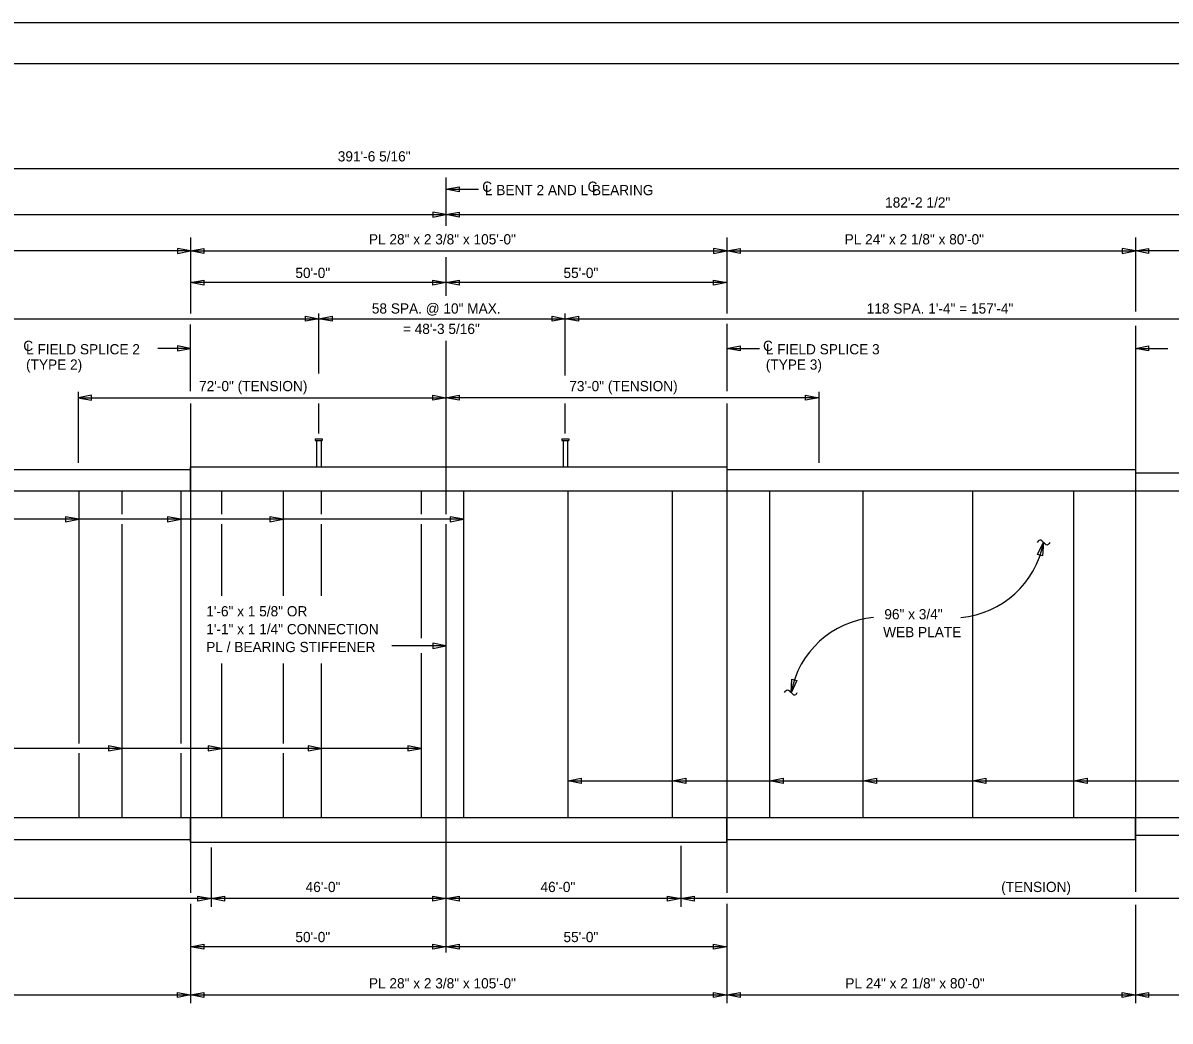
# Model space of a CAD drawing. Extents: x -305 to -161, y -187 to -99.
# Drawn here: x -251.8 to -195.7, y -148.4 to -99.5 of the extents above; entities that cross this region are included whole.
import ezdxf

# ---------------------------------------------------------------- set-up
doc = ezdxf.new("R2010")
doc.units = 0
for name, color, linetype in [('BR_AUTO DIMENSION', 7, 'Continuous'), ('BR_BORDER LINES', 7, 'Continuous'), ('BR_CENTER LINES', 7, 'Continuous'), ('BR_STRUCTURAL STEEL', 7, 'Continuous'), ('BR_TEXT', 7, 'Continuous'), ('Default', 7, 'Continuous'), ('Level 31', 7, 'Continuous')]:
    doc.layers.add(name, color=color, linetype=linetype)

msp = doc.modelspace()

# ---------------------------------------------------------------- linework, layer by layer
at = {"layer": 'BR_AUTO DIMENSION'}
for p, q in [((-284.516, -106.618), (-184.885, -106.618)), ((-231.124, -107.634), (-229.526, -107.634)), ((-284.516, -108.876), (-231.124, -108.876)), ((-231.124, -108.876), (-184.885, -108.876)), ((-243.624, -110.653), (-269.874, -110.653)), ((-243.624, -110.653), (-217.374, -110.653)), ((-217.374, -110.653), (-197.374, -110.653)), ((-184.885, -110.653), (-197.374, -110.653)), ((-231.124, -112.204), (-243.624, -112.204)), ((-217.374, -112.204), (-231.124, -112.204)), ((-278.349, -113.971), (-237.349, -113.971)), ((-237.349, -116.66), (-237.349, -113.721)), ((-237.349, -113.971), (-225.281, -113.971)), ((-225.281, -116.761), (-225.281, -113.721)), ((-225.281, -113.971), (-186.385, -113.971)), ((-243.624, -115.428), (-245.223, -115.428)), ((-217.374, -115.428), (-215.776, -115.428)), ((-197.374, -115.428), (-195.776, -115.428)), ((-249.124, -117.55), (-249.124, -121.025)), ((-249.124, -117.84), (-231.124, -117.84)), ((-212.874, -117.84), (-231.124, -117.84)), ((-212.874, -117.55), (-212.874, -121.025)), ((-237.349, -119.6), (-237.349, -118.13)), ((-225.281, -119.6), (-225.281, -118.13)), ((-230.266, -123.792), (-287.874, -123.792)), ((-231.124, -129.991), (-233.773, -129.991)), ((-232.34, -135.013), (-287.874, -135.013)), ((-225.147, -136.601), (-181.335, -136.601)), ((-219.624, -139.78), (-219.624, -142.773)), ((-242.624, -139.874), (-242.624, -142.773)), ((-242.624, -142.367), (-284.516, -142.367)), ((-231.124, -142.367), (-242.624, -142.367)), ((-219.624, -142.367), (-231.124, -142.367)), ((-184.885, -142.367), (-219.624, -142.367)), ((-231.124, -144.726), (-243.624, -144.726)), ((-217.374, -144.726), (-231.124, -144.726)), ((-269.874, -147.085), (-243.624, -147.085)), ((-243.624, -147.085), (-217.374, -147.085)), ((-217.374, -147.085), (-197.374, -147.085)), ((-197.374, -147.085), (-184.885, -147.085))]:
    msp.add_line(p, q, dxfattribs=at)
for points in [[(-230.474, -107.759), (-231.124, -107.634), (-230.474, -107.509)], [(-231.774, -109.001), (-231.124, -108.876), (-231.774, -108.751)], [(-230.474, -109.001), (-231.124, -108.876), (-230.474, -108.751)], [(-244.274, -110.778), (-243.624, -110.653), (-244.274, -110.528)], [(-242.974, -110.778), (-243.624, -110.653), (-242.974, -110.528)], [(-218.024, -110.778), (-217.374, -110.653), (-218.024, -110.528)], [(-216.724, -110.778), (-217.374, -110.653), (-216.724, -110.528)], [(-198.024, -110.778), (-197.374, -110.653), (-198.024, -110.528)], [(-196.724, -110.778), (-197.374, -110.653), (-196.724, -110.528)], [(-242.974, -112.329), (-243.624, -112.204), (-242.974, -112.079)], [(-231.774, -112.079), (-231.124, -112.204), (-231.774, -112.329)], [(-230.474, -112.329), (-231.124, -112.204), (-230.474, -112.079)], [(-218.024, -112.079), (-217.374, -112.204), (-218.024, -112.329)], [(-237.999, -113.846), (-237.349, -113.971), (-237.999, -114.096)], [(-236.699, -114.096), (-237.349, -113.971), (-236.699, -113.846)], [(-225.931, -113.846), (-225.281, -113.971), (-225.931, -114.096)], [(-224.631, -114.096), (-225.281, -113.971), (-224.631, -113.846)], [(-244.274, -115.553), (-243.624, -115.428), (-244.274, -115.303)], [(-216.724, -115.553), (-217.374, -115.428), (-216.724, -115.303)], [(-196.724, -115.553), (-197.374, -115.428), (-196.724, -115.303)], [(-248.474, -117.715), (-249.124, -117.84), (-248.474, -117.965)], [(-231.774, -117.715), (-231.124, -117.84), (-231.774, -117.965)], [(-230.474, -117.965), (-231.124, -117.84), (-230.474, -117.715)], [(-213.524, -117.715), (-212.874, -117.84), (-213.524, -117.965)], [(-249.749, -123.917), (-249.099, -123.792), (-249.749, -123.667)], [(-244.749, -123.917), (-244.099, -123.792), (-244.749, -123.667)], [(-239.749, -123.917), (-239.099, -123.792), (-239.749, -123.667)], [(-230.916, -123.917), (-230.266, -123.792), (-230.916, -123.667)], [(-202.159, -125.52), (-201.877, -124.922), (-201.917, -125.582)], [(-231.774, -130.116), (-231.124, -129.991), (-231.774, -129.866)], [(-213.946, -131.689), (-214.228, -132.287), (-214.188, -131.627)], [(-247.649, -135.138), (-246.999, -135.013), (-247.649, -134.888)], [(-242.763, -135.138), (-242.113, -135.013), (-242.763, -134.888)], [(-237.877, -135.138), (-237.227, -135.013), (-237.877, -134.888)], [(-232.99, -135.138), (-232.34, -135.013), (-232.99, -134.888)], [(-224.497, -136.726), (-225.147, -136.601), (-224.497, -136.476)], [(-219.378, -136.726), (-220.028, -136.601), (-219.378, -136.476)], [(-214.62, -136.726), (-215.27, -136.601), (-214.62, -136.476)], [(-210.045, -136.726), (-210.695, -136.601), (-210.045, -136.476)], [(-204.693, -136.726), (-205.343, -136.601), (-204.693, -136.476)], [(-199.729, -136.726), (-200.379, -136.601), (-199.729, -136.476)], [(-243.274, -142.242), (-242.624, -142.367), (-243.274, -142.492)], [(-241.974, -142.492), (-242.624, -142.367), (-241.974, -142.242)], [(-231.774, -142.242), (-231.124, -142.367), (-231.774, -142.492)], [(-230.474, -142.492), (-231.124, -142.367), (-230.474, -142.242)], [(-220.274, -142.242), (-219.624, -142.367), (-220.274, -142.492)], [(-218.974, -142.492), (-219.624, -142.367), (-218.974, -142.242)], [(-242.974, -144.851), (-243.624, -144.726), (-242.974, -144.601)], [(-231.774, -144.601), (-231.124, -144.726), (-231.774, -144.851)], [(-230.474, -144.851), (-231.124, -144.726), (-230.474, -144.601)], [(-218.024, -144.601), (-217.374, -144.726), (-218.024, -144.851)], [(-244.274, -146.96), (-243.624, -147.085), (-244.274, -147.21)], [(-242.974, -147.21), (-243.624, -147.085), (-242.974, -146.96)], [(-218.024, -146.96), (-217.374, -147.085), (-218.024, -147.21)], [(-216.724, -147.21), (-217.374, -147.085), (-216.724, -146.96)], [(-198.024, -146.96), (-197.374, -147.085), (-198.024, -147.21)], [(-196.724, -147.21), (-197.374, -147.085), (-196.724, -146.96)]]:
    msp.add_lwpolyline(points, close=True, dxfattribs=at)
for centre, start, end in [((-206.301, -124.118), 274.9624, 349.7037), ((-209.804, -133.091), 94.9624, 169.7037)]:
    msp.add_arc(centre, 4.497, start, end, dxfattribs=at)
at = {"layer": 'BR_BORDER LINES'}
msp.add_line((-163.178, -101.489), (-297.843, -101.489), dxfattribs=at)
at = {"layer": 'BR_CENTER LINES'}
for p, q in [((-231.124, -107.059), (-231.124, -109.43)), ((-243.624, -109.997), (-243.624, -113.711)), ((-217.374, -109.997), (-217.374, -113.711)), ((-197.374, -109.997), (-197.374, -113.625)), ((-231.124, -110.967), (-231.124, -112.846)), ((-243.645, -114.253), (-243.645, -117.526)), ((-217.374, -114.23), (-217.374, -117.526)), ((-197.374, -114.323), (-197.374, -142.045)), ((-231.124, -115.059), (-231.124, -122.412)), ((-243.624, -118.13), (-243.624, -124.614)), ((-217.374, -118.13), (-217.374, -126.436)), ((-243.624, -124.614), (-243.624, -142.086)), ((-217.374, -126.436), (-217.374, -142.086)), ((-231.124, -138.412), (-231.124, -145.014)), ((-243.624, -142.631), (-243.624, -147.486)), ((-217.374, -142.631), (-217.374, -147.486)), ((-197.374, -142.667), (-197.374, -147.486))]:
    msp.add_line(p, q, dxfattribs=at)
at = {"layer": 'BR_STRUCTURAL STEEL'}
for p, q in [((-243.624, -122.412), (-243.624, -121.225)), ((-243.624, -121.225), (-217.374, -121.225)), ((-217.374, -121.225), (-217.374, -122.412)), ((-269.874, -121.35), (-243.624, -121.35)), ((-217.374, -121.35), (-197.374, -121.35)), ((-197.374, -121.35), (-197.374, -122.412)), ((-184.885, -121.537), (-197.374, -121.537)), ((-184.885, -122.412), (-284.516, -122.412)), ((-249.099, -122.412), (-249.099, -134.771)), ((-246.999, -122.412), (-246.999, -123.55)), ((-244.099, -122.412), (-244.099, -134.771)), ((-242.113, -122.412), (-242.113, -123.55)), ((-239.099, -122.412), (-239.099, -127.548)), ((-237.227, -122.412), (-237.227, -123.55)), ((-232.34, -122.412), (-232.34, -123.55)), ((-231.124, -122.412), (-231.124, -123.55)), ((-230.266, -122.412), (-230.266, -138.412)), ((-225.147, -138.412), (-225.147, -122.412)), ((-220.028, -138.412), (-220.028, -122.412)), ((-215.27, -138.412), (-215.27, -122.412)), ((-210.695, -138.412), (-210.695, -122.412)), ((-205.343, -122.412), (-205.343, -138.412)), ((-200.379, -138.412), (-200.379, -122.412)), ((-246.999, -124.034), (-246.999, -138.412)), ((-242.113, -124.034), (-242.113, -127.548)), ((-237.227, -124.034), (-237.227, -127.548)), ((-232.34, -124.034), (-232.34, -129.618)), ((-231.124, -124.034), (-231.124, -138.412)), ((-232.34, -130.358), (-232.34, -138.412)), ((-242.113, -130.864), (-242.113, -138.412)), ((-239.099, -130.864), (-239.099, -134.771)), ((-237.227, -130.864), (-237.227, -138.412)), ((-249.099, -135.255), (-249.099, -138.412)), ((-244.099, -135.255), (-244.099, -138.412)), ((-239.099, -135.255), (-239.099, -138.412)), ((-184.885, -138.412), (-284.516, -138.412)), ((-243.624, -139.6), (-243.624, -138.412)), ((-217.374, -139.6), (-217.374, -138.412)), ((-197.374, -139.475), (-197.374, -138.412)), ((-269.874, -139.475), (-243.624, -139.475)), ((-243.624, -139.6), (-217.374, -139.6)), ((-217.374, -139.475), (-197.374, -139.475)), ((-184.885, -139.287), (-197.374, -139.287))]:
    msp.add_line(p, q, dxfattribs=at)
at = {"layer": 'BR_TEXT'}
for p, q in [((-202.137, -124.869), (-202.179, -124.93)), ((-201.795, -124.996), (-201.958, -124.847)), ((-201.562, -124.93), (-201.592, -124.976)), ((-214.543, -132.279), (-214.513, -132.233)), ((-214.31, -132.213), (-214.147, -132.362)), ((-213.968, -132.34), (-213.926, -132.279))]:
    msp.add_line(p, q, dxfattribs=at)
for centre, radius, start, end in [((-202.039, -124.922), 0.111, 43.4519, 151.7375), ((-201.702, -124.915), 0.125, 221.007, 330.8059), ((-214.403, -132.294), 0.125, 41.007, 150.8059), ((-214.066, -132.287), 0.111, 223.4519, 331.7375)]:
    msp.add_arc(centre, radius, start, end, dxfattribs=at)
at = {"layer": 'Default'}
for p, q in [((-237.521, -119.85), (-237.521, -119.944)), ((-237.521, -119.85), (-237.177, -119.85)), ((-237.521, -119.944), (-237.177, -119.944)), ((-237.459, -119.944), (-237.459, -121.225)), ((-237.24, -119.944), (-237.24, -121.225)), ((-237.177, -119.85), (-237.177, -119.944)), ((-225.453, -119.85), (-225.453, -119.944)), ((-225.453, -119.85), (-225.109, -119.85)), ((-225.453, -119.944), (-225.109, -119.944)), ((-225.39, -119.944), (-225.39, -121.225)), ((-225.171, -119.944), (-225.171, -121.225)), ((-225.109, -119.85), (-225.109, -119.944))]:
    msp.add_line(p, q, dxfattribs=at)
at = {"layer": 'Level 31'}
msp.add_lwpolyline([(-305.176, -187.489), (-161.176, -187.489), (-161.176, -99.489), (-305.176, -99.489)], close=True, dxfattribs=at)

# ---------------------------------------------------------------- texts
at = {"layer": 'BR_AUTO DIMENSION'}
for s, p in [('391\'-6 5/16"', (-236.42, -106.272)), ('182\'-2 1/2"', (-209.624, -108.53)), ('PL 28" x 2 3/8" x 105\'-0"', (-234.896, -110.334)), ('PL 24" x 2 1/8" x 80\'-0"', (-211.607, -110.334)), ('50\'-0"', (-238.496, -111.979)), ('55\'-0"', (-225.371, -111.979)), (' 73\'-0" (TENSION)', (-225.273, -117.521)), ('96" x 3/4" ', (-209.662, -128.694)), ('WEB PLATE', (-209.721, -129.569)), ('(TENSION)', (-203.941, -142.048)), ('46\'-0"', (-237.996, -142.048)), ('50\'-0"', (-238.496, -144.501)), ('55\'-0"', (-225.371, -144.501)), ('PL 28" x 2 3/8" x 105\'-0"', (-234.896, -146.766)), ('PL 24" x 2 1/8" x 80\'-0"', (-211.573, -146.766))]:
    msp.add_text(s, height=0.5, rotation=360, dxfattribs=at).set_placement(p)
for s, p in [('58 SPA. @ 10" MAX.', (-234.753, -113.721)), ('118 SPA. 1\'-4" = 157\'-4"', (-210.526, -113.721)), ('= 48\'-3 5/16"', (-233.233, -114.721)), (' 72\'-0" (TENSION)', (-243.398, -117.521)), ('46\'-0"', (-226.496, -142.048))]:
    msp.add_text(s, height=0.5, dxfattribs=at).set_placement(p)
at = {"layer": 'BR_TEXT'}
for s, p in [('C', (-229.351, -107.758)), ('C', (-224.192, -107.758)), ('L BENT 2 AND L BEARING', (-229.216, -107.924)), ('C', (-251.817, -115.551)), ('C', (-215.601, -115.551)), ('L FIELD SPLICE 2', (-251.682, -115.718)), ('L FIELD SPLICE 3', (-215.466, -115.718)), ('(TYPE 2)', (-251.682, -116.468)), ('(TYPE 3)', (-215.466, -116.468)), ('1\'-6" x 1 5/8" OR', (-242.862, -128.548)), ('1\'-1" x 1 1/4" CONNECTION ', (-242.862, -129.423)), ('PL / BEARING STIFFENER', (-242.862, -130.298))]:
    msp.add_text(s, height=0.5, rotation=360, dxfattribs=at).set_placement(p)

doc.saveas('drawing.dxf')
